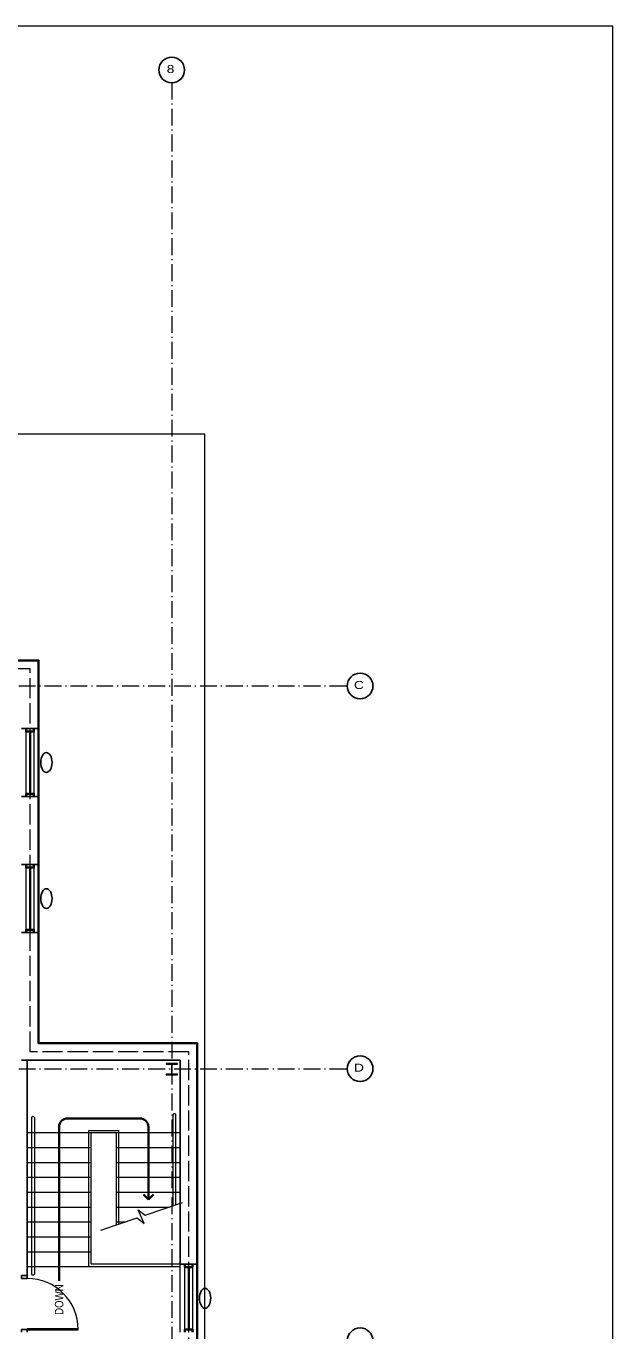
# Model space of a CAD drawing. Extents: x -118748 to -117136, y -118748 to -117596.
# Drawn here: x -117467 to -117136, y -118333 to -117596 of the extents above; entities that cross this region are included whole.
import ezdxf
from ezdxf.enums import TextEntityAlignment as Align

# ---------------------------------------------------------------- set-up
doc = ezdxf.new("R2010")
doc.units = 0
doc.header["$LTSCALE"] = 1.9
for name, pattern in [('DOT_DASHED', [7.7, 5, -1.2, 0.3, -1.2]), ('LONG_DASHED', [7.5, 6, -1.5]), ('MEDIUM_DASHED', [4.5, 3, -1.5])]:
    doc.linetypes.add(name, pattern=pattern)
for name, color, linetype, lineweight in [('10', 7, 'DOT_DASHED', 13), ('11', 7, 'Continuous', 25), ('12', 7, 'Continuous', 13), ('15', 7, 'Continuous', 13), ('16', 7, 'Continuous', 13), ('2', 7, 'Continuous', 35), ('20', 7, 'MEDIUM_DASHED', 13), ('23', 7, 'Continuous', 25), ('25', 7, 'Continuous', 13), ('26', 7, 'Continuous', 25), ('3', 7, 'Continuous', 35), ('40', 7, 'Continuous', 35), ('43', 7, 'Continuous', 25), ('46', 7, 'Continuous', 35), ('60', 7, 'LONG_DASHED', 13)]:
    doc.layers.add(name, color=color, linetype=linetype, lineweight=lineweight)

msp = doc.modelspace()

# ---------------------------------------------------------------- linework, layer by layer
at = {"layer": '10'}
for p, q in [((-117384.721, -117628.339), (-117384.721, -118698.41)), ((-118641.571, -117968.81), (-117285.521, -117968.81)), ((-118641.571, -118184.81), (-117285.521, -118184.81))]:
    msp.add_line(p, q, dxfattribs=at)
at = {"layer": '11'}
for centre in [(-117384.721, -117621.139), (-117278.321, -117968.81), (-117278.321, -118184.81), (-117278.321, -118338.41)]:
    msp.add_circle(centre, 7.253, dxfattribs=at)
at = {"layer": '12'}
msp.add_lwpolyline([(-117387.904, -118188.362), (-117381.488, -118188.362), (-117381.488, -118187.966), (-117384.572, -118187.966), (-117384.572, -118182.262), (-117381.488, -118182.262), (-117381.488, -118181.866), (-117387.904, -118181.866), (-117387.904, -118182.262), (-117384.82, -118182.262), (-117384.82, -118187.966), (-117387.904, -118187.966)], close=True, dxfattribs=at)
at = {"layer": '15', "lineweight": 25}
for p, q in [((-117459.921, -117954.41), (-117829.521, -117954.41)), ((-117459.921, -117992.81), (-117459.921, -117954.41)), ((-117469.521, -117992.81), (-117459.921, -117992.81)), ((-117469.521, -118031.21), (-117459.921, -118031.21)), ((-117459.921, -118069.61), (-117459.921, -118031.21)), ((-117469.521, -118069.61), (-117459.921, -118069.61)), ((-117469.521, -118108.01), (-117459.921, -118108.01)), ((-117459.921, -118170.41), (-117459.921, -118108.01)), ((-117370.321, -118170.41), (-117459.921, -118170.41)), ((-117370.321, -118295.21), (-117370.321, -118170.41)), ((-117379.921, -118180.01), (-117469.521, -118180.01)), ((-117379.921, -118295.21), (-117379.921, -118180.01)), ((-117379.921, -118295.21), (-117370.321, -118295.21))]:
    msp.add_line(p, q, dxfattribs=at)
at = {"layer": '16'}
for p, q in [((-117459.921, -117992.81), (-117459.921, -118031.21)), ((-117466.902, -118029.61), (-117466.902, -117994.41)), ((-117462.539, -117994.41), (-117462.539, -118029.61)), ((-117466.902, -118106.41), (-117466.902, -118071.21)), ((-117462.539, -118071.21), (-117462.539, -118106.41)), ((-117459.921, -118069.61), (-117459.921, -118108.01)), ((-117379.921, -118333.61), (-117379.921, -118295.21)), ((-117377.303, -118332.01), (-117377.303, -118296.81)), ((-117372.939, -118296.81), (-117372.939, -118332.01)), ((-117370.321, -118295.21), (-117370.321, -118333.61))]:
    msp.add_line(p, q, dxfattribs=at)
at = {"layer": '16', "lineweight": 35}
for p, q in [((-117464.721, -117994.41), (-117464.721, -118029.61)), ((-117464.721, -118071.21), (-117464.721, -118106.41)), ((-117375.121, -118332.01), (-117375.121, -118296.81))]:
    msp.add_line(p, q, dxfattribs=at)
for points in [[(-117462.539, -117992.81), (-117462.539, -117994.41), (-117466.902, -117994.41), (-117466.902, -117992.81)], [(-117462.539, -118031.21), (-117462.539, -118029.61), (-117466.902, -118029.61), (-117466.902, -118031.21)], [(-117462.539, -118069.61), (-117462.539, -118071.21), (-117466.902, -118071.21), (-117466.902, -118069.61)], [(-117462.539, -118108.01), (-117462.539, -118106.41), (-117466.902, -118106.41), (-117466.902, -118108.01)], [(-117377.303, -118295.21), (-117377.303, -118296.81), (-117372.939, -118296.81), (-117372.939, -118295.21)], [(-117377.303, -118333.61), (-117377.303, -118332.01), (-117372.939, -118332.01), (-117372.939, -118333.61)]]:
    msp.add_lwpolyline(points, dxfattribs=at)
at = {"layer": '2', "lineweight": 13}
msp.add_lwpolyline([(-118748.365, -118748.365), (-117365.965, -118748.365), (-117365.965, -117826.765), (-118748.365, -117826.765), (-118748.365, -118748.365), (-117135.565, -118748.365), (-117135.565, -117596.365), (-118748.365, -117596.365)], close=True, dxfattribs=at)
at = {"layer": '20', "linetype": 'Continuous'}
for p, q in [((-117466.321, -118296.489), (-117466.321, -118180.01)), ((-117466.321, -118180.01), (-117379.921, -118180.01)), ((-117379.921, -118260.774), (-117379.921, -118180.01)), ((-117463.921, -118212.36), (-117463.921, -118300.696)), ((-117462.321, -118212.36), (-117462.321, -118300.696)), ((-117383.921, -118262.124), (-117383.921, -118210.811)), ((-117382.321, -118261.584), (-117382.321, -118210.811)), ((-117466.321, -118220.889), (-117430.321, -118220.889)), ((-117430.321, -118294.889), (-117430.321, -118220.889)), ((-117430.321, -118220.889), (-117415.921, -118220.889)), ((-117415.921, -118220.889), (-117379.921, -118220.889)), ((-117415.921, -118272.924), (-117415.921, -118220.889)), ((-117466.321, -118229.289), (-117430.321, -118229.289)), ((-117415.921, -118229.289), (-117379.921, -118229.289)), ((-117466.321, -118237.689), (-117430.321, -118237.689)), ((-117415.921, -118237.689), (-117379.921, -118237.689)), ((-117466.321, -118246.089), (-117430.321, -118246.089)), ((-117415.921, -118246.089), (-117379.921, -118246.089)), ((-117466.321, -118254.489), (-117430.321, -118254.489)), ((-117415.921, -118254.489), (-117379.921, -118254.489)), ((-117466.321, -118262.889), (-117430.321, -118262.889)), ((-117415.921, -118262.889), (-117386.188, -118262.889)), ((-117466.321, -118271.289), (-117430.321, -118271.289)), ((-117415.921, -118271.289), (-117411.076, -118271.289)), ((-117401.359, -118271.289), (-117400.636, -118271.289)), ((-117379.921, -118296.489), (-117379.921, -118268.373)), ((-117466.321, -118279.689), (-117430.321, -118279.689)), ((-117466.321, -118288.089), (-117430.321, -118288.089)), ((-117430.321, -118294.889), (-117379.921, -118294.889)), ((-117466.321, -118296.489), (-117430.321, -118296.489)), ((-117431.521, -118296.489), (-117379.921, -118296.489))]:
    msp.add_line(p, q, dxfattribs=at)
for points in [[(-117431.521, -118296.489), (-117431.521, -118219.689), (-117414.721, -118219.689), (-117414.721, -118272.519)], [(-117424.78, -118275.914), (-117404.276, -118268.994), (-117400.257, -118272.156), (-117403.638, -118264.432), (-117399.755, -118267.468), (-117378.598, -118260.327)]]:
    msp.add_lwpolyline(points, dxfattribs=at)
for centre, major_axis, ratio, start_param, end_param in [((-117463.121, -118212.319), (0.803, 0), 0.613441, 6.1980757, 9.5098878), ((-117383.121, -118210.769), (0.803, 0), 0.617028, 6.1980754, 9.5098875), ((-117463.121, -118300.738), (-0.803, 0), 0.613441, 6.1980754, 9.5098875)]:
    msp.add_ellipse(centre, major_axis=major_axis, ratio=ratio, start_param=start_param, end_param=end_param, dxfattribs=at)
at = {"layer": '23'}
for p, q in [((-117469.521, -118180.01), (-117466.321, -118180.01)), ((-117466.321, -118301.61), (-117466.321, -118180.01)), ((-117466.321, -118301.61), (-117469.521, -118301.61))]:
    msp.add_line(p, q, dxfattribs=at)
at = {"layer": '25', "lineweight": 40}
msp.add_line((-117437.521, -118332.01), (-117466.321, -118332.01), dxfattribs=at)
at = {"layer": '25'}
msp.add_arc((-117466.321, -118332.01), 28.8, 359.99998, 89.99998, dxfattribs=at)
at = {"layer": '26'}
for points in [[(-117466.321, -118301.61), (-117466.321, -118303.21), (-117469.521, -118303.21), (-117469.521, -118301.61)], [(-117469.521, -118333.61), (-117469.521, -118332.01), (-117466.321, -118332.01), (-117466.321, -118333.61)]]:
    msp.add_lwpolyline(points, dxfattribs=at)
at = {"layer": '3'}
msp.add_lwpolyline([(-118098.321, -117954.41), (-117829.521, -117954.41), (-117459.921, -117954.41), (-117459.921, -118170.41), (-117370.321, -118170.41), (-117370.321, -118352.81), (-117459.921, -118352.81), (-117459.921, -118645.61), (-117704.721, -118645.61), (-117704.721, -118592.81), (-117847.121, -118592.81), (-117850.321, -118592.801), (-117860.744, -118590.984), (-117862.249, -118590.443), (-117871.571, -118585.668), (-117872.847, -118584.703), (-117880.323, -118577.368), (-117881.254, -118576.067), (-117886.205, -118566.837), (-117886.706, -118565.318), (-117888.682, -118555.032), (-117888.707, -118553.433), (-117890.316, -118553.433)], dxfattribs=at)
at = {"layer": '40'}
for p, q in [((-117443.521, -118212.889), (-117402.721, -118212.889)), ((-117448.321, -118304.489), (-117448.321, -118217.689)), ((-117397.921, -118217.689), (-117397.921, -118258.689))]:
    msp.add_line(p, q, dxfattribs=at)
for centre, start, end in [((-117443.521, -118217.689), 90, 180), ((-117402.721, -118217.689), 0, 90)]:
    msp.add_arc(centre, 4.8, start, end, dxfattribs=at)
at = {"layer": '43'}
for centre in [(-117455.521, -118012.01), (-117455.521, -118088.81), (-117365.921, -118314.41)]:
    msp.add_ellipse(centre, major_axis=(0, -5.6), ratio=0.571429, dxfattribs=at)
at = {"layer": '46'}
for q in [(-117400.749, -118255.86), (-117395.092, -118255.86)]:
    msp.add_line((-117397.921, -118258.689), q, dxfattribs=at)
at = {"layer": '60'}
for points in [[(-117464.721, -118175.21), (-117464.721, -117959.21), (-118501.521, -117959.21)], [(-117375.121, -118348.01), (-117375.121, -118175.21), (-117464.721, -118175.21)]]:
    msp.add_lwpolyline(points, dxfattribs=at)

# ---------------------------------------------------------------- texts
at = {"layer": '11', "width": 1.3}
for s, p in [(' 8 ', (-117385.401, -117622.84)), (' C ', (-117279.001, -117970.51)), (' D ', (-117279.001, -118186.51))]:
    msp.add_text(s, height=4.518, dxfattribs=at).set_placement(p, align=Align.CENTER)
at = {"layer": '46', "width": 0.85}
msp.add_text('DOWN', height=4.8, rotation=90, dxfattribs=at).set_placement((-117445.921, -118306.527), align=Align.RIGHT)

doc.saveas('drawing.dxf')
